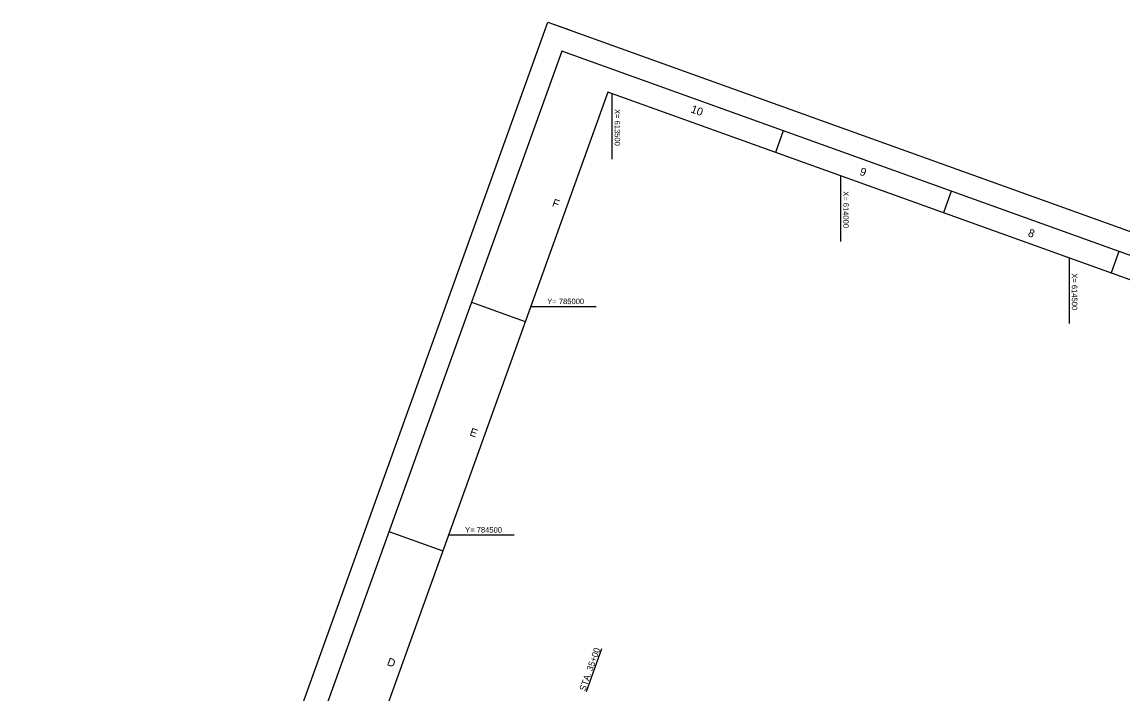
# Model space of a CAD drawing. Extents: x 612209 to 617500, y 780934 to 785622.
# Drawn here: x 612209 to 614617, y 784152 to 785622 of the extents above; entities that cross this region are included whole.
import ezdxf

# ---------------------------------------------------------------- set-up
doc = ezdxf.new("R2010")
doc.units = 0
for name, color, linetype in [('G-ANNO-NPLT', 7, 'Continuous'), ('G-ANNO-TTLB', 7, 'Continuous'), ('V-ALGN-TEXT', 7, 'Continuous'), ('V-TOPO-COOR-STAT', 7, 'Continuous')]:
    doc.layers.add(name, color=color, linetype=linetype)

msp = doc.modelspace()

# ---------------------------------------------------------------- linework, layer by layer
at = {"layer": 'G-ANNO-NPLT'}
msp.add_lwpolyline([(613359.5, 785622.2), (617500, 784133.6), (616349.7, 780934.1), (612209.2, 782422.8)], close=True, dxfattribs=at)
msp.add_lwpolyline([(613342.6, 785575.2), (613359.5, 785622.2), (613406.6, 785605.3)], dxfattribs=at)
at = {"layer": 'G-ANNO-TTLB'}
for p, q in [((613874.3, 785384), (613857.4, 785337)), ((614241.3, 785252.1), (614224.4, 785205)), ((614241.3, 785252.1), (614224.4, 785205)), ((614608.3, 785120.1), (614591.4, 785073.1)), ((613192.3, 785009.2), (613309.9, 784966.9)), ((613011.8, 784507.3), (613129.5, 784465))]:
    msp.add_line(p, q, dxfattribs=at)
for points in [[(612273.2, 782452.9), (616319.6, 780998.1), (617436.1, 784103.5), (613389.7, 785558.3)], [(617372.1, 784073.3), (613490.4, 785468.9), (612407.7, 782457.7), (616289.5, 781062.1)]]:
    msp.add_lwpolyline(points, close=True, dxfattribs=at)
at = {"layer": 'V-ALGN-TEXT'}
msp.add_line((613443.9, 784157.3), (613477.7, 784251.4), dxfattribs=at)
at = {"layer": 'V-TOPO-COOR-STAT'}
for p, q in [((613500, 785322), (613500, 785465.5)), ((614000, 785142.2), (614000, 785285.7)), ((614500, 784962.5), (614500, 785105.9)), ((613321.8, 785000), (613465.2, 785000)), ((613142, 784500), (613285.5, 784500))]:
    msp.add_line(p, q, dxfattribs=at)

# ---------------------------------------------------------------- texts
at = {"layer": 'G-ANNO-TTLB'}
for s, p in [('10', (613670.6, 785424.8)), ('9', (614040, 785288.2)), ('F', (613367.3, 785219.5)), ('8', (614408.1, 785154.2)), ('E', (613186.9, 784718.3)), ('D', (613006.3, 784215.5))]:
    msp.add_text(s, height=17.5, rotation=340.2251, dxfattribs=at).set_placement(p)
at = {"layer": 'V-ALGN-TEXT'}
msp.add_text('STA. 35+00', height=13.92, rotation=70.2251, dxfattribs=at).set_placement((613440.9, 784157.2))
at = {"layer": 'V-TOPO-COOR-STAT'}
for s, p in [('X= 613500', (613505.4, 785431.9)), ('X= 614000', (614005.4, 785252.1)), ('X= 614500', (614505.4, 785072.4))]:
    msp.add_text(s, height=12, rotation=270, dxfattribs=at).set_placement(p)
for s, p in [('Y= 785000', (613358.1, 785005)), ('Y= 784500', (613178.4, 784505))]:
    msp.add_text(s, height=12, dxfattribs=at).set_placement(p)

doc.saveas('drawing.dxf')
